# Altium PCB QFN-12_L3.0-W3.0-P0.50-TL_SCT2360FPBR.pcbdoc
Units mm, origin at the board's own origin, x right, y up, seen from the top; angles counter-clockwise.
Board outline 16.94 x 16.5 mm, 2 copper layers (Top Layer, Bottom Layer), stack 0 mm thick; 1 components, 0 nets, 12 pads, 0 vias.
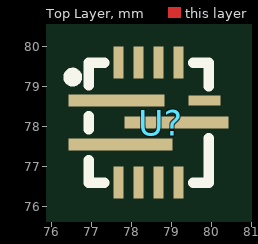
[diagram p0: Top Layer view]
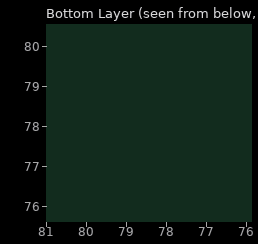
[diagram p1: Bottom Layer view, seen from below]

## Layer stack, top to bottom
Top Layer: signal copper (thickness not stored)
Bottom Layer: signal copper (thickness not stored)

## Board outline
86.791,69.85 69.85,69.85 69.85,86.35 86.791,86.35

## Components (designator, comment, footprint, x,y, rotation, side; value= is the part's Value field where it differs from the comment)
U? "" QFN-12_L3.0-W3.0-P0.50-TL_SCT2360FPBR 78.741,78.1 r0 top

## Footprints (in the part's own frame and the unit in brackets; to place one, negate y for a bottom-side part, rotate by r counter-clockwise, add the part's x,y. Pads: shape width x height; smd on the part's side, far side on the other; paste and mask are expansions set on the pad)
QFN-12_L3.0-W3.0-P0.50-TL_SCT2360FPBR [mm]
  rect 2.4x0.3 smd: 1(-1.1,0.55)
  rect 2.6x0.3 smd: 2(-1,-0.55) 7(0.4,0)
  rect 0.25x0.8 smd: 3(-1.05,-1.5) 4(-0.55,-1.5) 5(-0.05,-1.5) 6(0.45,-1.5) 9(0.45,1.5) 10(-0.05,1.5) 11(-0.55,1.5) 12(-1.05,1.5)
  rect 0.8x0.25 smd: 8(1.1,0.55)
  silkscreen extent -2.31,-1.5 1.2,1.5

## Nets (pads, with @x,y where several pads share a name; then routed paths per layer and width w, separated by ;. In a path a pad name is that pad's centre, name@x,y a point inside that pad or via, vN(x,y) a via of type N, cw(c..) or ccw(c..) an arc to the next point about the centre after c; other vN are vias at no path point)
pads on no net: U?.1 U?.2 U?.3 U?.4 U?.5 U?.6 U?.7 U?.8 U?.9 U?.10 U?.11 U?.12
